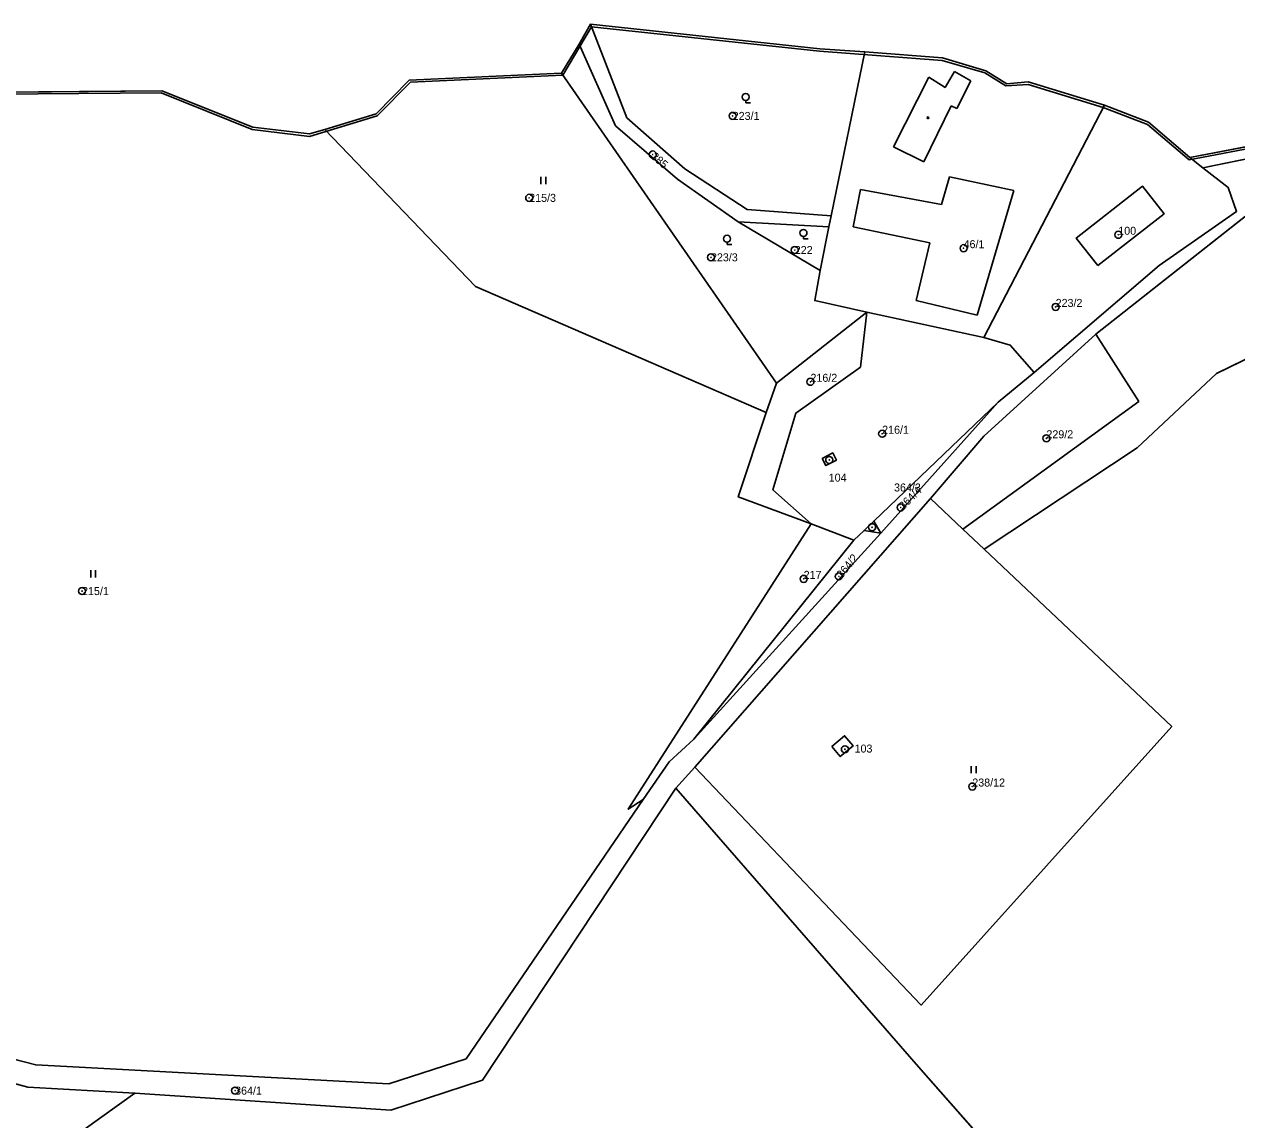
# Model space of a CAD drawing. Extents: x -652854 to -650068, y -1097661 to -1095417.
# Drawn here: x -651554.5 to -651296.9, y -1096100 to -1095867.2 of the extents above; entities that cross this region are included whole.
import ezdxf

# ---------------------------------------------------------------- set-up
doc = ezdxf.new("R2010")
doc.units = 0
for name, color, linetype in [('Definiční body parcel', 7, 'Continuous'), ('Hranice - vnitř_ kresba', 7, 'Continuous'), ('Hranice obcí', 7, 'Continuous'), ('Hranice parcel', 7, 'Continuous'), ('Obvody jako plochy', 7, 'Continuous'), ('Ostatní hranice', 7, 'Continuous'), ('Parcelní čísla', 7, 'Continuous'), ('Prvky pro prodl_ par_ č_', 7, 'Continuous'), ('Značky kultur', 7, 'Continuous'), ('Značky na budově ne v SPI', 7, 'Continuous')]:
    doc.layers.add(name, color=color, linetype=linetype)

msp = doc.modelspace()

# ---------------------------------------------------------------- linework, layer by layer
at = {"layer": 'Definiční body parcel'}
for centre, radius in [((-651403.97, -1095886.66), 0.75), ((-651403.97, -1095886.66), 0.0327), ((-651420.95, -1095894.86), 0.75), ((-651420.95, -1095894.86), 0.0327), ((-651447.21, -1095904.07), 0.75), ((-651447.21, -1095904.07), 0.0327), ((-651322.04, -1095911.92), 0.75), ((-651322.04, -1095911.92), 0.0327), ((-651390.78, -1095915.16), 0.75), ((-651354.91, -1095914.77), 0.75), ((-651354.91, -1095914.77), 0.0327), ((-651408.59, -1095916.71), 0.75), ((-651408.59, -1095916.71), 0.0327), ((-651390.78, -1095915.16), 0.0327), ((-651335.35, -1095927.25), 0.75), ((-651335.35, -1095927.25), 0.0327), ((-651387.45, -1095943.16), 0.75), ((-651387.45, -1095943.16), 0.0327), ((-651372.21, -1095954.2), 0.75), ((-651372.21, -1095954.2), 0.0327), ((-651337.31, -1095955.16), 0.75), ((-651337.31, -1095955.16), 0.0327), ((-651383.46, -1095959.77), 0.75), ((-651383.46, -1095959.77), 0.0327), ((-651368.28, -1095969.87), 0.75), ((-651368.28, -1095969.87), 0.0327), ((-651374.35, -1095974.07), 0.75), ((-651374.35, -1095974.07), 0.0327), ((-651388.89, -1095985.04), 0.75), ((-651381.42, -1095984.51), 0.75), ((-651542.22, -1095987.63), 0.75), ((-651388.89, -1095985.04), 0.0327), ((-651381.42, -1095984.51), 0.0327), ((-651542.22, -1095987.63), 0.0327), ((-651380.13, -1096021.25), 0.75), ((-651380.13, -1096021.25), 0.0327), ((-651353.06, -1096029.17), 0.75), ((-651353.06, -1096029.17), 0.0327), ((-651509.7, -1096093.79), 0.75), ((-651509.7, -1096093.79), 0.0327)]:
    msp.add_circle(centre, radius, dxfattribs=at)
at = {"layer": 'Hranice - vnitř_ kresba'}
for p, q in [((-651362.32, -1095878.41), (-651369.78, -1095893.2)), ((-651358.84, -1095880.6), (-651362.32, -1095878.41)), ((-651356.81, -1095877.21), (-651358.84, -1095880.6)), ((-651353.34, -1095879.24), (-651356.81, -1095877.21)), ((-651356.36, -1095885.05), (-651353.34, -1095879.24)), ((-651363.37, -1095896.45), (-651357.56, -1095884.53)), ((-651357.56, -1095884.53), (-651356.36, -1095885.05)), ((-651369.78, -1095893.2), (-651363.37, -1095896.45)), ((-651357.94, -1095899.62), (-651359.6, -1095905.5)), ((-651344.21, -1095902.49), (-651357.94, -1095899.62)), ((-651376.8, -1095902.33), (-651378.38, -1095910.26)), ((-651359.6, -1095905.5), (-651376.8, -1095902.33)), ((-651352.06, -1095928.97), (-651344.21, -1095902.49)), ((-651378.38, -1095910.26), (-651362.09, -1095913.65)), ((-651362.09, -1095913.65), (-651364.96, -1095925.88)), ((-651364.96, -1095925.88), (-651352.06, -1095928.97))]:
    msp.add_line(p, q, dxfattribs=at)
at = {"layer": 'Hranice obcí'}
for p, q in [((-651436.62, -1095871.42), (-651434.21, -1095867.18)), ((-651434.21, -1095867.18), (-651385.46, -1095872.37)), ((-651440.38, -1095877.6), (-651436.62, -1095871.42)), ((-651385.46, -1095872.37), (-651375.93, -1095873.06)), ((-651375.93, -1095873.06), (-651359.4, -1095874.34)), ((-651359.4, -1095874.34), (-651350.22, -1095877.05)), ((-651472.7, -1095879.06), (-651440.38, -1095877.6)), ((-651350.22, -1095877.05), (-651345.75, -1095879.82)), ((-651572.18, -1095881.74), (-651525.28, -1095881.3)), ((-651525.28, -1095881.3), (-651505.92, -1095889.03)), ((-651479.75, -1095886.2), (-651472.7, -1095879.06)), ((-651345.75, -1095879.82), (-651341.18, -1095879.44)), ((-651341.18, -1095879.44), (-651324.99, -1095884.4)), ((-651490.62, -1095889.58), (-651479.75, -1095886.2)), ((-651324.99, -1095884.4), (-651315.65, -1095887.98)), ((-651505.92, -1095889.03), (-651493.9, -1095890.5)), ((-651315.65, -1095887.98), (-651306.87, -1095895.47)), ((-651306.87, -1095895.47), (-651261.23, -1095886.87)), ((-651493.9, -1095890.5), (-651490.62, -1095889.58))]:
    msp.add_line(p, q, dxfattribs=at)
at = {"layer": 'Hranice parcel'}
for p, q in [((-651426.44, -1095887.05), (-651434.21, -1095867.18)), ((-651436.62, -1095871.42), (-651428.88, -1095888.76)), ((-651375.93, -1095873.06), (-651383.03, -1095907.86)), ((-651394.66, -1095943.45), (-651440.38, -1095877.6)), ((-651350.62, -1095933.77), (-651324.99, -1095884.4)), ((-651428.88, -1095888.76), (-651415.7, -1095900.11)), ((-651414.11, -1095897.91), (-651426.44, -1095887.05)), ((-651304.11, -1095897.7), (-651257.1, -1095888.1)), ((-651458.6, -1095922.89), (-651490.62, -1095889.58)), ((-651304.11, -1095897.7), (-651306.87, -1095895.47)), ((-651400.93, -1095906.58), (-651414.11, -1095897.91)), ((-651298.68, -1095901.85), (-651304.11, -1095897.7)), ((-651415.7, -1095900.11), (-651402.81, -1095909.17)), ((-651330.98, -1095912.63), (-651316.87, -1095901.61)), ((-651326.79, -1095933.01), (-651286.04, -1095900.87)), ((-651316.87, -1095901.61), (-651312.31, -1095907.44)), ((-651296.92, -1095906.96), (-651298.68, -1095901.85)), ((-651383.03, -1095907.86), (-651400.93, -1095906.58)), ((-651313.37, -1095918.47), (-651296.92, -1095906.96)), ((-651402.81, -1095909.17), (-651383.51, -1095910.22)), ((-651402.81, -1095909.17), (-651385.4, -1095919.5)), ((-651383.03, -1095907.86), (-651383.51, -1095910.22)), ((-651312.31, -1095907.44), (-651326.42, -1095918.46)), ((-651383.51, -1095910.22), (-651385.4, -1095919.5)), ((-651326.42, -1095918.46), (-651330.98, -1095912.63)), ((-651385.4, -1095919.5), (-651386.53, -1095925.92)), ((-651339.88, -1095941.15), (-651313.37, -1095918.47)), ((-651256.73, -1095919.7), (-651301.18, -1095941.4)), ((-651396.83, -1095949.66), (-651458.6, -1095922.89)), ((-651386.53, -1095925.92), (-651375.49, -1095928.33)), ((-651375.49, -1095928.33), (-651394.66, -1095943.45)), ((-651376.8, -1095940.03), (-651375.49, -1095928.33)), ((-651375.49, -1095928.33), (-651350.62, -1095933.77)), ((-651344.99, -1095935.4), (-651350.62, -1095933.77)), ((-651350.58, -1095954.73), (-651326.79, -1095933.01)), ((-651339.88, -1095941.15), (-651344.99, -1095935.4)), ((-651326.79, -1095933.01), (-651317.71, -1095947.34)), ((-651390.57, -1095949.81), (-651376.8, -1095940.03)), ((-651347.55, -1095947.52), (-651339.88, -1095941.15)), ((-651301.18, -1095941.4), (-651318.03, -1095957.19)), ((-651396.83, -1095949.66), (-651394.66, -1095943.45)), ((-651374.01, -1095972.77), (-651347.55, -1095947.52)), ((-651372.52, -1095975.35), (-651347.55, -1095947.52)), ((-651317.71, -1095947.34), (-651355.05, -1095974.51)), ((-651402.78, -1095967.62), (-651396.83, -1095949.66)), ((-651395.43, -1095966.12), (-651390.57, -1095949.81)), ((-651361.92, -1095967.93), (-651350.58, -1095954.73)), ((-651382.73, -1095958.28), (-651384.98, -1095959.48)), ((-651381.93, -1095959.78), (-651382.73, -1095958.28)), ((-651318.03, -1095957.19), (-651350.52, -1095978.76)), ((-651384.98, -1095959.48), (-651384.18, -1095960.98)), ((-651384.18, -1095960.98), (-651381.93, -1095959.78)), ((-651387.28, -1095973.31), (-651395.43, -1095966.12)), ((-651361.92, -1095967.93), (-651412.03, -1096025.02)), ((-651387.28, -1095973.31), (-651402.78, -1095967.62)), ((-651355.05, -1095974.51), (-651361.92, -1095967.93)), ((-651426.15, -1096034.01), (-651387.28, -1095973.31)), ((-651378.21, -1095976.78), (-651387.28, -1095973.31)), ((-651376.07, -1095974.74), (-651374.01, -1095972.77)), ((-651372.52, -1095975.35), (-651374.01, -1095972.77)), ((-651412.23, -1096019.12), (-651372.52, -1095975.35)), ((-651378.21, -1095976.78), (-651376.07, -1095974.74)), ((-651372.52, -1095975.35), (-651376.07, -1095974.74)), ((-651350.52, -1095978.76), (-651355.05, -1095974.51)), ((-651412.23, -1096019.12), (-651378.21, -1095976.78)), ((-651310.69, -1096016.4), (-651350.52, -1095978.76)), ((-651363.92, -1096075.6), (-651310.69, -1096016.4)), ((-651417.5, -1096023.91), (-651412.23, -1096019.12)), ((-651380.2, -1096018.39), (-651382.92, -1096020.67)), ((-651378.4, -1096020.53), (-651380.2, -1096018.39)), ((-651382.92, -1096020.67), (-651381.12, -1096022.82)), ((-651381.12, -1096022.82), (-651378.4, -1096020.53)), ((-651422.98, -1096031.89), (-651417.5, -1096023.91)), ((-651416.03, -1096029.53), (-651412.03, -1096025.02)), ((-651412.03, -1096025.02), (-651363.92, -1096075.6)), ((-651457.12, -1096091.57), (-651416.03, -1096029.53)), ((-651364.46, -1096088.73), (-651416.03, -1096029.53)), ((-651460.64, -1096087.01), (-651422.98, -1096031.89)), ((-651422.98, -1096031.89), (-651426.15, -1096034.01)), ((-651575.74, -1096082.25), (-651552.06, -1096088.31)), ((-651577.07, -1096086.78), (-651553.76, -1096093.05)), ((-651477.04, -1096092.34), (-651460.64, -1096087.01)), ((-651552.06, -1096088.31), (-651477.04, -1096092.34)), ((-651306.45, -1096154.54), (-651364.46, -1096088.73)), ((-651476.63, -1096097.91), (-651457.12, -1096091.57)), ((-651553.76, -1096093.05), (-651530.98, -1096094.3)), ((-651530.98, -1096094.3), (-651541.77, -1096102.05)), ((-651530.98, -1096094.3), (-651476.63, -1096097.91))]:
    msp.add_line(p, q, dxfattribs=at)
at = {"layer": 'Obvody jako plochy'}
for points in [[(-651383.03, -1095907.86), (-651400.93, -1095906.58), (-651414.11, -1095897.91), (-651426.44, -1095887.05), (-651434.21, -1095867.18), (-651436.62, -1095871.42), (-651428.88, -1095888.76), (-651415.7, -1095900.11), (-651402.81, -1095909.17), (-651383.51, -1095910.22)], [(-651434.21, -1095867.18), (-651426.44, -1095887.05), (-651414.11, -1095897.91), (-651400.93, -1095906.58), (-651383.03, -1095907.86), (-651375.93, -1095873.06), (-651385.46, -1095872.37)], [(-651440.38, -1095877.6), (-651394.66, -1095943.45), (-651375.49, -1095928.33), (-651386.53, -1095925.92), (-651385.4, -1095919.5), (-651402.81, -1095909.17), (-651415.7, -1095900.11), (-651428.88, -1095888.76), (-651436.62, -1095871.42)], [(-651375.49, -1095928.33), (-651350.62, -1095933.77), (-651324.99, -1095884.4), (-651341.18, -1095879.44), (-651345.75, -1095879.82), (-651350.22, -1095877.05), (-651359.4, -1095874.34), (-651375.93, -1095873.06), (-651383.03, -1095907.86), (-651383.51, -1095910.22), (-651385.4, -1095919.5), (-651386.53, -1095925.92)], [(-651490.62, -1095889.58), (-651458.6, -1095922.89), (-651396.83, -1095949.66), (-651394.66, -1095943.45), (-651440.38, -1095877.6), (-651472.7, -1095879.06), (-651479.75, -1095886.2)], [(-651525.28, -1095881.3), (-651572.18, -1095881.74), (-651578.18, -1095896.33), (-651682.58, -1096047.12), (-651647.14, -1096066.13), (-651602.07, -1096071.45), (-651575.74, -1096082.25), (-651552.06, -1096088.31), (-651477.04, -1096092.34), (-651460.64, -1096087.01), (-651422.98, -1096031.89), (-651426.15, -1096034.01), (-651387.28, -1095973.31), (-651402.78, -1095967.62), (-651396.83, -1095949.66), (-651458.6, -1095922.89), (-651490.62, -1095889.58), (-651493.9, -1095890.5), (-651505.92, -1095889.03)], [(-651339.88, -1095941.15), (-651313.37, -1095918.47), (-651296.92, -1095906.96), (-651298.68, -1095901.85), (-651304.11, -1095897.7), (-651306.87, -1095895.47), (-651315.65, -1095887.98), (-651324.99, -1095884.4), (-651350.62, -1095933.77), (-651344.99, -1095935.4)], [(-651261.23, -1095886.87), (-651306.87, -1095895.47), (-651304.11, -1095897.7), (-651257.1, -1095888.1)], [(-651326.42, -1095918.46), (-651312.31, -1095907.44), (-651316.87, -1095901.61), (-651330.98, -1095912.63)], [(-651326.42, -1095918.46), (-651330.98, -1095912.63), (-651316.87, -1095901.61), (-651312.31, -1095907.44)], [(-651383.51, -1095910.22), (-651402.81, -1095909.17), (-651385.4, -1095919.5)], [(-651375.49, -1095928.33), (-651394.66, -1095943.45), (-651396.83, -1095949.66), (-651402.78, -1095967.62), (-651387.28, -1095973.31), (-651395.43, -1095966.12), (-651390.57, -1095949.81), (-651376.8, -1095940.03)], [(-651375.49, -1095928.33), (-651376.8, -1095940.03), (-651390.57, -1095949.81), (-651395.43, -1095966.12), (-651387.28, -1095973.31), (-651378.21, -1095976.78), (-651376.07, -1095974.74), (-651374.01, -1095972.77), (-651347.55, -1095947.52), (-651339.88, -1095941.15), (-651344.99, -1095935.4), (-651350.62, -1095933.77)], [(-651350.58, -1095954.73), (-651361.92, -1095967.93), (-651355.05, -1095974.51), (-651317.71, -1095947.34), (-651326.79, -1095933.01)], [(-651374.01, -1095972.77), (-651372.52, -1095975.35), (-651347.55, -1095947.52)], [(-651384.98, -1095959.48), (-651384.18, -1095960.98), (-651381.93, -1095959.78), (-651382.73, -1095958.28)], [(-651384.98, -1095959.48), (-651382.73, -1095958.28), (-651381.93, -1095959.78), (-651384.18, -1095960.98)], [(-651350.52, -1095978.76), (-651355.05, -1095974.51), (-651361.92, -1095967.93), (-651412.03, -1096025.02), (-651363.92, -1096075.6), (-651310.69, -1096016.4)], [(-651422.98, -1096031.89), (-651417.5, -1096023.91), (-651412.23, -1096019.12), (-651378.21, -1095976.78), (-651387.28, -1095973.31), (-651426.15, -1096034.01)], [(-651376.07, -1095974.74), (-651372.52, -1095975.35), (-651374.01, -1095972.77)], [(-651412.23, -1096019.12), (-651372.52, -1095975.35), (-651376.07, -1095974.74), (-651378.21, -1095976.78)], [(-651382.92, -1096020.67), (-651381.12, -1096022.82), (-651378.4, -1096020.53), (-651380.2, -1096018.39)], [(-651382.92, -1096020.67), (-651380.2, -1096018.39), (-651378.4, -1096020.53), (-651381.12, -1096022.82)], [(-651530.98, -1096094.3), (-651541.77, -1096102.05), (-651515.89, -1096111.76), (-651477.76, -1096123.05), (-651402.13, -1096149.83), (-651380.6, -1096157.11), (-651353.91, -1096173.45), (-651337.3, -1096188.34), (-651319.7, -1096183.32), (-651311.55, -1096175.64), (-651306.45, -1096154.54), (-651364.46, -1096088.73), (-651416.03, -1096029.53), (-651457.12, -1096091.57), (-651476.63, -1096097.91)]]:
    msp.add_lwpolyline(points, close=True, dxfattribs=at)
for points in [[(-651257.1, -1095888.1), (-651304.11, -1095897.7), (-651298.68, -1095901.85), (-651296.92, -1095906.96), (-651313.37, -1095918.47), (-651339.88, -1095941.15), (-651347.55, -1095947.52), (-651372.52, -1095975.35), (-651412.23, -1096019.12), (-651417.5, -1096023.91), (-651422.98, -1096031.89), (-651460.64, -1096087.01), (-651477.04, -1096092.34), (-651552.06, -1096088.31), (-651575.74, -1096082.25)], [(-651577.07, -1096086.78), (-651553.76, -1096093.05), (-651530.98, -1096094.3), (-651476.63, -1096097.91), (-651457.12, -1096091.57), (-651416.03, -1096029.53), (-651412.03, -1096025.02), (-651361.92, -1095967.93), (-651350.58, -1095954.73), (-651326.79, -1095933.01), (-651286.04, -1095900.87)], [(-651286.04, -1095900.87), (-651326.79, -1095933.01), (-651317.71, -1095947.34), (-651355.05, -1095974.51), (-651350.52, -1095978.76), (-651318.03, -1095957.19), (-651301.18, -1095941.4), (-651256.73, -1095919.7)], [(-651256.73, -1095919.7), (-651301.18, -1095941.4), (-651318.03, -1095957.19), (-651350.52, -1095978.76), (-651310.69, -1096016.4), (-651363.92, -1096075.6), (-651412.03, -1096025.02), (-651416.03, -1096029.53), (-651364.46, -1096088.73), (-651306.45, -1096154.54), (-651311.55, -1096175.64), (-651319.7, -1096183.32), (-651337.3, -1096188.34), (-651353.91, -1096173.45), (-651380.6, -1096157.11), (-651402.13, -1096149.83), (-651477.76, -1096123.05), (-651515.89, -1096111.76), (-651541.77, -1096102.05), (-651530.98, -1096094.3), (-651553.76, -1096093.05), (-651577.07, -1096086.78)]]:
    msp.add_lwpolyline(points, dxfattribs=at)
at = {"layer": 'Ostatní hranice'}
for p, q in [((-651440.04, -1095877.98), (-651433.94, -1095867.72)), ((-651433.94, -1095867.72), (-651385.53, -1095872.87)), ((-651385.53, -1095872.87), (-651359.45, -1095874.85)), ((-651359.45, -1095874.85), (-651350.38, -1095877.54)), ((-651472.42, -1095879.49), (-651440.04, -1095877.98)), ((-651350.38, -1095877.54), (-651345.92, -1095880.3)), ((-651479.52, -1095886.65), (-651472.42, -1095879.49)), ((-651345.92, -1095880.3), (-651341.21, -1095879.95)), ((-651341.21, -1095879.95), (-651325.24, -1095884.86)), ((-651571.86, -1095882.13), (-651525.43, -1095881.79)), ((-651525.43, -1095881.79), (-651506.07, -1095889.52)), ((-651325.24, -1095884.86), (-651315.83, -1095888.46)), ((-651493.86, -1095891.01), (-651479.52, -1095886.65)), ((-651315.83, -1095888.46), (-651306.96, -1095895.96)), ((-651306.96, -1095895.96), (-651260.97, -1095887.31)), ((-651506.07, -1095889.52), (-651493.86, -1095891.01))]:
    msp.add_line(p, q, dxfattribs=at)
at = {"layer": 'Značky kultur'}
for p, q in [((-651401.21, -1095883.39), (-651401.21, -1095883.89)), ((-651401.21, -1095883.89), (-651400.187, -1095883.89)), ((-651444.717, -1095899.635), (-651444.717, -1095901.135)), ((-651443.695, -1095901.135), (-651443.695, -1095899.635)), ((-651388.94, -1095912.28), (-651388.94, -1095912.78)), ((-651405.18, -1095913.51), (-651405.18, -1095914.01)), ((-651405.18, -1095914.01), (-651404.157, -1095914.01)), ((-651388.94, -1095912.78), (-651387.917, -1095912.78)), ((-651540.357, -1095983.225), (-651540.357, -1095984.725)), ((-651539.335, -1095984.725), (-651539.335, -1095983.225)), ((-651353.267, -1096024.825), (-651353.267, -1096026.325)), ((-651352.245, -1096026.325), (-651352.245, -1096024.825))]:
    msp.add_line(p, q, dxfattribs=at)
for centre in [(-651401.21, -1095882.64), (-651405.18, -1095912.76), (-651388.94, -1095911.53)]:
    msp.add_circle(centre, 0.75, dxfattribs=at)
at = {"layer": 'Značky na budově ne v SPI'}
msp.add_circle((-651362.46, -1095887.05), 0.175, dxfattribs=at)

# ---------------------------------------------------------------- texts
at = {"layer": 'Parcelní čísla'}
for s, height, p in [('223/1', 1.7, (-651403.97, -1095887.51)), ('215/3', 1.7, (-651447.21, -1095904.92)), ('100', 1.7, (-651322.04, -1095911.92)), ('222', 1.7, (-651390.78, -1095916.01)), ('46/1', 1.7, (-651354.91, -1095914.77)), ('223/3', 1.7, (-651408.59, -1095917.56)), ('223/2', 1.7, (-651335.35, -1095927.25)), ('216/2', 1.7, (-651387.45, -1095943.16)), ('216/1', 1.7, (-651372.21, -1095954.2)), ('229/2', 1.7, (-651337.31, -1095955.16)), ('104', 0.1, (-651383.46, -1095959.77)), ('364/3', 0.1, (-651374.35, -1095974.12)), ('217', 1.7, (-651388.89, -1095985.04)), ('215/1', 1.7, (-651542.22, -1095988.48)), ('103', 0.1, (-651380.13, -1096021.25)), ('238/12', 1.7, (-651353.06, -1096029.17)), ('364/1', 1.7, (-651509.7, -1096094.64))]:
    msp.add_text(s, height=height, dxfattribs=at).set_placement(p)
for s, rotation, p in [('385', 319.347, (-651421.504, -1095895.505)), ('364/4', 45, (-651367.679, -1095970.471)), ('364/2', 51.192, (-651380.758, -1095985.043))]:
    msp.add_text(s, height=1.7, rotation=rotation, dxfattribs=at).set_placement(p)
at = {"layer": 'Prvky pro prodl_ par_ č_'}
for s, p in [('104', (-651383.57, -1095964.38)), ('364/3', (-651369.69, -1095966.47)), ('103', (-651378.08, -1096021.95))]:
    msp.add_text(s, height=1.7, dxfattribs=at).set_placement(p)

doc.saveas('drawing.dxf')
